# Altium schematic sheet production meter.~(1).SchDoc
size A4
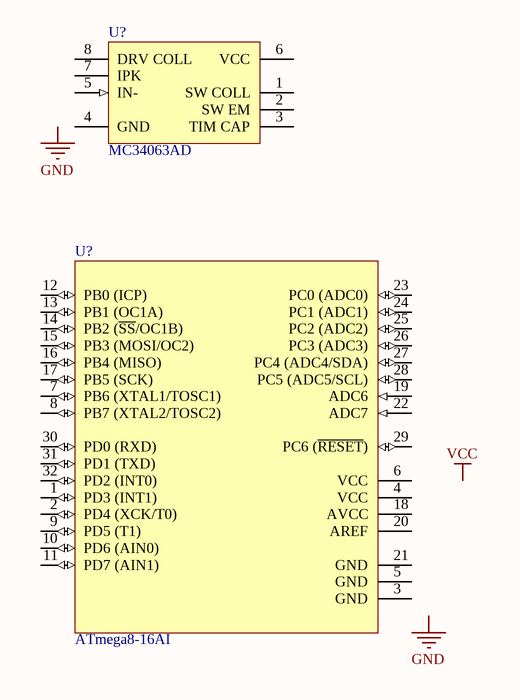
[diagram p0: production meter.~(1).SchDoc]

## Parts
(Parts that share a designator on the sheet are numbered #1, #2 ... from top to bottom, then left to right.)
U?#1  MC34063AD  [751-05_M]
U?#2  ATmega8-16AI  [32A_N]

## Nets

Not connected (* = marked no-connect by the designer): U?#1 1(SW_COLL) 2(SW_EM) 3(TIM_CAP) 4(GND) 5(IN-) 6(VCC) 7(IPK) 8(DRV_COLL); U?#2 1(PD3_(INT1)) 2(PD4_(XCK/T0)) 3(GND) 4(VCC) 5(GND) 6(VCC) 7(PB6_(XTAL1/TOSC1)) 8(PB7_(XTAL2/TOSC2)) 9(PD5_(T1)) 10(PD6_(AIN0)) 11(PD7_(AIN1)) 12(PB0_(ICP)) 13(PB1_(OC1A)) 14(PB2_(~{SS}/OC1B)) 15(PB3_(MOSI/OC2)) 16(PB4_(MISO)) 17(PB5_(SCK)) 18(AVCC) 19(ADC6) 20(AREF) 21(GND) 22(ADC7) 23(PC0_(ADC0)) 24(PC1_(ADC1)) 25(PC2_(ADC2)) 26(PC3_(ADC3)) 27(PC4_(ADC4/SDA)) 28(PC5_(ADC5/SCL)) 29(PC6_(~{RESET})) 30(PD0_(RXD)) 31(PD1_(TXD)) 32(PD2_(INT0))

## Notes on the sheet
- Labels drawn without touching a wire or pin: GND, VCC

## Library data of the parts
U?#1 = MC34063AD: DC-to-DC Converter Control Circuit
U?#2 = ATmega8-16AI: 8-Bit AVR Microcontroller with 8K Bytes of In-System Programmable Flash Memory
